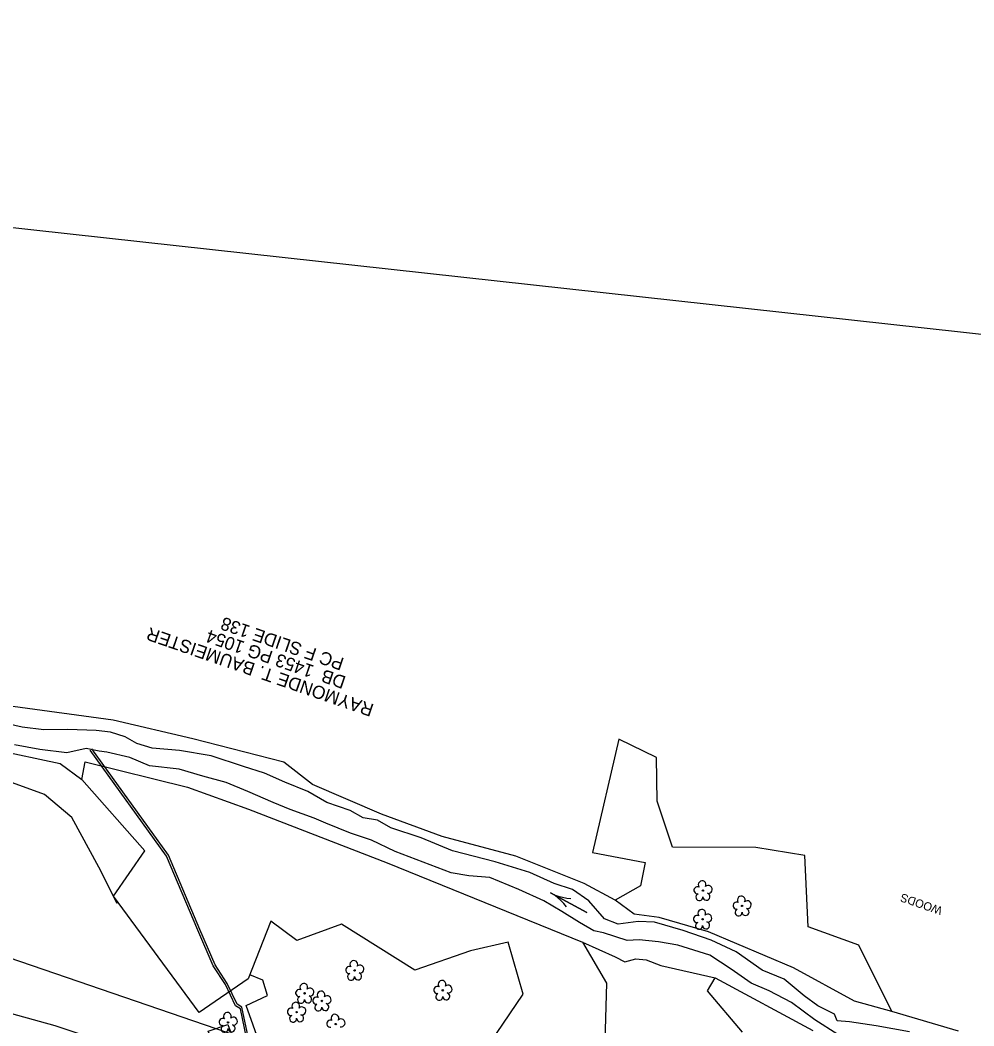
# Model space of a CAD drawing. Extents: x 472260 to 482161, y 489063 to 507124.
# Drawn here: x 480089.5 to 480548.3, y 493450.2 to 493934.2 of the extents above; entities that cross this region are included whole.
import ezdxf

# ---------------------------------------------------------------- set-up
doc = ezdxf.new("R2010")
doc.units = 0
for name, color, linetype in [('Exist Structure Minor Drop Inlet Cogo Elevation', 7, 'Continuous'), ('Exist Structure Minor Drop Inlet Cogo Number', 7, 'Continuous'), ('Prop Drainage Structure Drop Inlet Grate 2 Wide Slots and Flat Grates 840 20 Label', 7, 'Continuous'), ('Prop Drainage Structure Pipe RCP 18in Class IV', 7, 'Continuous'), ('Prop Drainage Structure Pipe RCP 24in Class III', 7, 'Continuous'), ('Prop Drainage Structure Pipe RCP 66in Class III', 7, 'Continuous'), ('Prop Drainage Structure Pipe Welded Steel 66in Label', 7, 'Continuous'), ('Prop Drainage Structure Tops and Inverts LABEL', 7, 'Continuous'), ('Prop Erosion Rip Rap Pad at Outlet Label', 7, 'Continuous'), ('Scratch_Level_7', 7, 'Continuous')]:
    doc.layers.add(name, color=color, linetype=linetype)

msp = doc.modelspace()

# ---------------------------------------------------------------- linework, layer by layer
at = {"layer": 'Exist Structure Minor Drop Inlet Cogo Elevation'}
msp.add_line((480529.09, 493330.54), (479902.03, 493545.37), dxfattribs=at)
at = {"layer": 'Exist Structure Minor Drop Inlet Cogo Number'}
msp.add_line((480638.53, 493773.45), (479176.25, 493934.19), dxfattribs=at)
at = {"layer": 'Prop Drainage Structure Drop Inlet Grate 2 Wide Slots and Flat Grates 840 20 Label'}
for p, q in [((480417.95, 493515.26), (480417.95, 493515.26)), ((480436.75, 493507.92), (480436.75, 493507.92)), ((480417.76, 493501.47), (480417.76, 493501.47)), ((480250.38, 493476.9), (480250.38, 493476.9)), ((480226.32, 493465.85), (480226.32, 493465.85)), ((480292.79, 493467.29), (480292.79, 493467.29)), ((480234.6, 493462.16), (480234.6, 493462.16)), ((480222.45, 493456.79), (480222.45, 493456.79)), ((480189.52, 493451.87), (480189.52, 493451.87)), ((480241.3, 493451.04), (480241.3, 493451.04))]:
    msp.add_line(p, q, dxfattribs=at)
for centre in [(480417.95, 493515.26), (480436.75, 493507.92), (480417.76, 493501.47), (480250.38, 493476.9), (480226.32, 493465.85), (480292.79, 493467.29), (480234.6, 493462.16), (480222.45, 493456.79), (480189.52, 493451.87), (480241.3, 493451.04)]:
    msp.add_circle(centre, 0.326, dxfattribs=at)
for centre, radius, start, end in [((480417.56, 493518.13), 1.86, 330.1651, 219.7134), ((480415.34, 493515.41), 1.73, 62.6636, 279.3457), ((480420.5, 493515.85), 1.9, 257.1011, 134.1999), ((480416.24, 493512.14), 1.69, 111.5671, 6.231), ((480419.62, 493512.36), 1.7, 181.2822, 74.56), ((480434.15, 493508.07), 1.73, 62.6636, 279.3457), ((480436.37, 493510.79), 1.86, 330.1651, 219.7134), ((480439.3, 493508.51), 1.9, 257.1011, 134.1999), ((480417.37, 493504.34), 1.86, 330.1651, 219.7134), ((480435.05, 493504.8), 1.69, 111.5671, 6.231), ((480438.43, 493505.02), 1.7, 181.2822, 74.56), ((480415.15, 493501.62), 1.73, 62.6636, 279.3457), ((480416.05, 493498.35), 1.69, 111.5671, 6.231), ((480419.43, 493498.57), 1.7, 181.2822, 74.56), ((480420.3, 493502.05), 1.9, 257.1011, 134.1999), ((480250, 493479.77), 1.86, 330.1651, 219.7134), ((480247.78, 493477.05), 1.73, 62.6636, 279.3457), ((480248.68, 493473.78), 1.69, 111.5671, 6.231), ((480252.06, 493474), 1.7, 181.2822, 74.56), ((480252.93, 493477.49), 1.9, 257.1011, 134.1999), ((480225.94, 493468.72), 1.86, 330.1651, 219.7134), ((480292.4, 493470.17), 1.86, 330.1651, 219.7134), ((480223.72, 493466), 1.73, 62.6636, 279.3457), ((480228.87, 493466.44), 1.9, 257.1011, 134.1999), ((480234.21, 493465.03), 1.86, 330.1651, 219.7134), ((480290.18, 493467.45), 1.73, 62.6636, 279.3457), ((480291.08, 493464.17), 1.69, 111.5671, 6.231), ((480294.46, 493464.39), 1.7, 181.2822, 74.56), ((480295.34, 493467.88), 1.9, 257.1011, 134.1999), ((480222.06, 493459.67), 1.86, 330.1651, 219.7134), ((480224.62, 493462.73), 1.69, 111.5671, 6.231), ((480228, 493462.95), 1.7, 181.2822, 74.56), ((480231.99, 493462.31), 1.73, 62.6636, 279.3457), ((480236.27, 493459.26), 1.7, 181.2822, 74.56), ((480237.15, 493462.74), 1.9, 257.1011, 134.1999), ((480189.13, 493454.75), 1.86, 330.1651, 219.7134), ((480219.84, 493456.95), 1.73, 62.6636, 279.3457), ((480225, 493457.38), 1.9, 257.1011, 134.1999), ((480232.89, 493459.03), 1.69, 111.5671, 6.231), ((480186.91, 493452.03), 1.73, 62.6636, 279.3457), ((480192.07, 493452.46), 1.9, 257.1011, 134.1999), ((480220.75, 493453.67), 1.69, 111.5671, 6.231), ((480224.12, 493453.89), 1.7, 181.2822, 74.56), ((480238.69, 493451.2), 1.73, 62.6636, 279.3457), ((480240.91, 493453.92), 1.86, 330.1651, 219.7134), ((480243.85, 493451.63), 1.9, 257.1011, 134.1999), ((480187.81, 493448.75), 1.69, 111.5671, 6.231), ((480191.19, 493448.98), 1.7, 181.2822, 74.56)]:
    msp.add_arc(centre, radius, start, end, dxfattribs=at)
at = {"layer": 'Prop Drainage Structure Pipe RCP 18in Class IV'}
msp.add_line((480353.35, 493509.47), (480353.35, 493509.47), dxfattribs=at)
msp.add_lwpolyline([(480352.26, 493507.46), (480350.97, 493509.05), (480349.54, 493510.54), (480347.97, 493511.93), (480346.31, 493513.18), (480344.54, 493514.22), (480362.15, 493504.73), (480344.54, 493514.22), (480346.38, 493513.31), (480348.34, 493512.61), (480350.36, 493512.06), (480352.4, 493511.69), (480354.43, 493511.49)], dxfattribs=at)
at = {"layer": 'Prop Drainage Structure Pipe RCP 24in Class III'}
for points in [[(480517.37, 493447.3), (480501.2, 493450.26), (480488.39, 493452.16), (480482.56, 493452.6), (480481.16, 493455.85), (480473.24, 493459.88), (480466.58, 493464.69), (480456.97, 493472.69), (480446.35, 493477.05), (480433.89, 493485.79), (480421.89, 493491.38), (480408.48, 493496.12), (480394.65, 493500.06), (480386.75, 493500.46), (480377.14, 493499.11), (480370.66, 493501.7), (480363, 493510.28), (480355.17, 493515.82), (480346.44, 493518.76), (480334.65, 493524.04), (480318.03, 493529.16), (480297.43, 493534.4), (480282.41, 493540.62), (480267.75, 493545.56), (480261.45, 493549.14), (480254.5, 493550.33), (480248.17, 493553.8), (480237.05, 493557.74), (480227.93, 493563.02), (480216.73, 493567.44), (480207.06, 493571.74), (480196.98, 493574.98), (480181.44, 493580.19), (480166.2, 493582.67), (480152.97, 493583.77), (480145.6, 493586.15), (480140.03, 493589.3), (480132.93, 493591.59), (480126.09, 493592.31), (480112.43, 493592.79), (480100.93, 493592.67), (480090.36, 493593.86), (480078.22, 493596.65)], [(480482.77, 493446.1), (480471.78, 493453.02), (480460.55, 493461.5), (480449.84, 493466.97), (480441.06, 493470.75), (480431.53, 493477.41), (480421.33, 493484.19), (480405.85, 493488.96), (480396.63, 493490.7), (480387.24, 493491.55), (480381.51, 493491.25), (480370.05, 493494.9), (480365.47, 493495.96), (480358.54, 493499.94), (480350.05, 493505.29), (480341.33, 493510.31), (480329.41, 493515.74), (480315.38, 493521.59), (480305.3, 493522.44), (480296.74, 493523.82), (480269.84, 493534.06), (480258.44, 493539.61), (480248.35, 493542.96), (480236.52, 493547.79), (480230.86, 493550.18), (480219.44, 493554.36), (480211.13, 493557.67), (480199, 493562.93), (480188.57, 493567.36), (480177.28, 493570.41), (480165.95, 493573.69), (480151.73, 493575.31), (480142.19, 493579.39), (480131.14, 493581.86), (480127.49, 493582.35), (480121.17, 493583.63), (480111.98, 493581.63), (480098.89, 493583.12), (480086.75, 493585.36)], [(480201.29, 493422.33), (480200.26, 493435.2), (480200.26, 493435.2), (480200.26, 493435.2), (480200.26, 493435.2), (480195.45, 493458.42), (480193.06, 493459.87), (480188.26, 493470.02), (480182.33, 493479.11), (480175.01, 493496.21), (480159.92, 493531.87), (480123.08, 493582.87)], [(480202.29, 493422.41), (480201.26, 493435.16), (480201.26, 493435.16), (480201.26, 493435.16), (480201.26, 493435.16), (480196.14, 493459.17), (480193.84, 493460.57), (480189.13, 493470.51), (480183.21, 493479.59), (480175.93, 493496.6), (480160.79, 493532.37), (480123.89, 493583.46)]]:
    msp.add_lwpolyline(points, dxfattribs=at)
at = {"layer": 'Prop Drainage Structure Tops and Inverts LABEL'}
for points in [[(480037.28, 493595.46), (480076.92, 493583.19), (480108.77, 493576.45), (480119.15, 493568.71)], [(480136.16, 493509.14), (480127.35, 493526.64), (480114.4, 493550.4), (480101.18, 493561.49), (480080.52, 493569.14), (480056.96, 493576.34), (480041.9, 493583.13), (480028.35, 493591.21)], [(480508.77, 493457.15), (480490.82, 493462.01), (480461.46, 493478.06), (480420.69, 493495.52), (480396.94, 493502.39), (480384.86, 493503.9), (480375.77, 493510.66)], [(480359.92, 493490.4), (480375.79, 493483.36), (480380.39, 493481.05), (480385.61, 493482.46), (480390.57, 493481.98), (480397.73, 493479.32), (480423.79, 493473.35)], [(479985.49, 493488.15), (480026.37, 493475.35), (480067.14, 493461.19), (480106.19, 493450.33), (480170.01, 493429.21), (480186.08, 493422.99), (480187.07, 493432), (480179.88, 493447.68), (480189.41, 493450.79), (480199.73, 493422.85), (480212.53, 493419.89), (480198.26, 493460.01), (480208.49, 493464.79), (480206.21, 493472.24), (480199.94, 493474.71)]]:
    msp.add_lwpolyline(points, dxfattribs=at)
at = {"layer": 'Prop Erosion Rip Rap Pad at Outlet Label'}
for points in [[(480540.92, 493447.58), (480508.77, 493457.15), (480492.94, 493489.07), (480468.63, 493497.9), (480466.93, 493532.21), (480443.4, 493535.98), (480403.26, 493536.26), (480395.84, 493558.28), (480395.61, 493579.26), (480377.51, 493588.16), (480364.74, 493533.56), (480390.2, 493528.75), (480387.9, 493517.6), (480375.77, 493510.66), (480360.76, 493518.67), (480327.98, 493531.78), (480292.49, 493541.26), (480263.38, 493552.08), (480230.03, 493566.38), (480216.33, 493577.07), (480172.54, 493588.25), (480134.14, 493597.38), (480085.92, 493603.82), (480048.01, 493615.8)], [(480305.87, 493427.51), (480331.4, 493465.44), (480324.16, 493490.53), (480306.15, 493486.34), (480279.41, 493476.94), (480244.06, 493499.15), (480222.57, 493491.34), (480210.09, 493500.6), (480199.19, 493472.8), (480175.55, 493456.59), (480134.39, 493512.53), (480149.51, 493534.4), (480119.15, 493568.71), (480120.75, 493577.28), (480169.99, 493565.01), (480199.4, 493554.45), (480266, 493528.69), (480359.92, 493490.4), (480371.59, 493470.74), (480370.4, 493431.51)], [(480436.9, 493447.09), (480420.06, 493467.1), (480423.79, 493473.35), (480470.83, 493447.97)]]:
    msp.add_lwpolyline(points, dxfattribs=at)

# ---------------------------------------------------------------- texts
at = {"layer": 'Prop Drainage Structure Pipe RCP 66in Class III'}
msp.add_text('WOODS', height=4, rotation=160.9619, dxfattribs=at).set_placement((480533.47, 493507.25))
at = {"layer": 'Prop Drainage Structure Pipe Welded Steel 66in Label'}
for s, p in [('PC F SLIDE 138', (480245.75, 493626.98)), ('DB  1453 PG 1054', (480246.65, 493618.14))]:
    msp.add_text(s, height=6.25, rotation=160.9892, dxfattribs=at).set_placement(p)
at = {"layer": 'Scratch_Level_7'}
msp.add_text('RAYMONDE T. BAUMEISTER', height=6.25, rotation=160.9892, dxfattribs=at).set_placement((480260.05, 493604.75))

doc.saveas('drawing.dxf')
